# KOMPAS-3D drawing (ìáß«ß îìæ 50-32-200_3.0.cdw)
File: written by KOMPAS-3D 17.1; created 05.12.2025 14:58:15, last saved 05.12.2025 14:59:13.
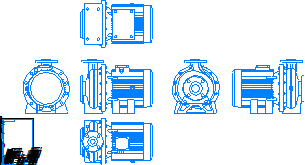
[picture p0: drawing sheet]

Sheet 1: A4, portrait

Title block, sheet 1: name: Насос МНС / 50-32-200_3.0; material: Сталь 10  ГОСТ 1050-88; mass: 135,17; sheets: 1; sheet format: A4

Views: Вид 1, Спереди, Проекционный вид 2, Проекционный вид 4, Проекционный вид 5, Проекционный вид 6
Referenced files in \\adlc.lan\data\АДЛ_ПКД\3D-модели\ADL production\Насосы ГРАНПАМП\Насосы ГРАНПАМП серии МНС\KOMPAS 3D\: Насос МНС 50-32-200_3.0.m3d
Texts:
  Andrey
  АДЛ
Dimensions and other numbers on the sheet: 1:1; 1; 50-32-200_3.0; 135,17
